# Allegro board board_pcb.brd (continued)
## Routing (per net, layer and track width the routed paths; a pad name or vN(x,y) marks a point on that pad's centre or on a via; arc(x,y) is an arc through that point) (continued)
FMC_D15: length 45.5
  TOP w0.152: U1.T16 v2(58.07,69.25) ; U2.R2 v2(72.49,69.63)
  ART08 w0.114: v2(72.49,69.63) 73.16,69.63 73.28,69.75 73.28,70.76 73.05,70.99 72.63,70.99 72.52,70.88 72.52,70.17 72.41,70.05 72.18,70.05 72.06,70.17 72.06,70.88 71.95,70.99 71.24,70.99 71.12,71.11 71.12,72.12 71.01,72.24 70.78,72.24 70.67,72.12 70.67,71.11 70.55,70.99 70.32,70.99 70.21,71.11 70.21,72.12 70.09,72.24 69.87,72.24 69.75,72.12 69.75,71.11 69.64,70.99 69.41,70.99 69.29,71.11 69.29,72.12 69.18,72.24 68.95,72.24 68.84,72.12 68.84,71.11 68.72,70.99 68.49,70.99 68.38,71.11 68.38,72.12 68.27,72.24 68.04,72.24 67.92,72.12 67.92,71.11 67.81,70.99 67.58,70.99 67.47,71.11 67.47,72.12 67.35,72.24 67.12,72.24 67.01,72.12 67.01,71.11 66.89,70.99 66.67,70.99 66.55,71.11 66.55,72.12 66.44,72.24 66.21,72.24 66.09,72.12 66.09,71.11 65.98,70.99 65.75,70.99 65.64,71.11 65.64,72.12 65.52,72.24 65.29,72.24 65.18,72.12 65.18,71.11 65.07,70.99 64.84,70.99 64.72,71.11 64.72,72.12 64.61,72.24 64.38,72.24 64.27,72.12 64.27,71.11 64.15,70.99 62.22,70.99 62.1,71.11 62.1,71.97 61.99,72.09 61.76,72.09 61.64,71.97 61.64,71.11 61.53,70.99 61.3,70.99 61.19,71.11 61.19,71.97 61.07,72.09 60.84,72.09 60.73,71.97 60.73,71.11 60.62,70.99 60.39,70.99 60.27,71.11 60.27,71.97 60.16,72.09 59.93,72.09 59.81,71.97 59.81,71.11 59.7,70.99 59.41,70.99 59.3,70.88 59.3,69.08 59.05,68.83 58.48,68.83 v2(58.07,69.25)
FMC_D16: length 45.6
  TOP w0.152: U1.T13 v2(58.07,66.85) ; U2.E8 v2(68.48,60.83)
  ART08 w0.114: v2(58.07,66.85) 57.83,66.85 57.42,66.43 57.06,66.43 56.87,66.24 56.87,65.89 56.62,65.63 56.26,65.63 56.06,65.43 56.06,65.07 55.83,64.85 55.45,64.85 55.12,64.52 55.12,60.96 55.24,60.83 55.93,60.83 56.08,60.68 56.08,59.44 56.29,59.23 56.81,59.23 57.02,59.44 57.39,59.44 57.71,59.12 57.71,58.56 57.82,58.45 58.07,58.45 58.19,58.56 58.19,59.58 58.3,59.69 58.53,59.69 58.64,59.58 58.64,58.56 58.76,58.45 59.11,58.45 59.23,58.56 59.23,59.6 59.34,59.72 59.57,59.72 59.69,59.6 59.69,58.18 59.8,58.06 60.09,58.06 60.21,58.18 60.21,58.48 60.32,58.6 60.55,58.6 60.66,58.48 60.66,58.18 60.78,58.06 61.15,58.06 61.26,58.18 61.26,59.6 61.38,59.72 61.61,59.72 61.72,59.6 61.72,58.18 61.83,58.06 62.06,58.06 62.18,58.18 62.18,59.6 62.29,59.72 62.52,59.72 62.63,59.6 62.63,58.18 62.75,58.06 62.98,58.06 63.09,58.18 63.09,59.6 63.21,59.72 63.43,59.72 63.55,59.6 63.55,58.18 63.66,58.06 63.89,58.06 64.01,58.18 64.01,59.6 64.12,59.72 64.35,59.72 64.46,59.6 64.46,58.18 64.58,58.06 64.88,58.06 65,58.18 65,59.61 66.62,61.24 67.33,61.24 67.45,61.13 67.45,60.9 67.56,60.78 67.79,60.78 67.9,60.9 67.9,61.13 68.02,61.24 68.37,61.24 68.48,61.13 v2(68.48,60.83)
FMC_D17: length 45.7
  TOP w0.152: U1.R13 v2(57.27,66.85) ; U2.D7 v2(69.28,60.03)
  ART08 w0.114: v2(57.27,66.85) 57.04,66.85 56.64,66.45 54.89,66.45 54.74,66.29 54.74,64.77 54.56,64.59 53.92,64.59 53.77,64.44 53.77,64.16 53.89,64.04 54.6,64.04 54.71,63.93 54.71,63.7 54.6,63.59 53.89,63.59 53.77,63.47 53.77,63.24 53.89,63.13 54.6,63.13 54.71,63.01 54.71,62.79 54.6,62.67 53.89,62.67 53.77,62.56 53.77,62.33 53.89,62.21 54.6,62.21 54.71,62.1 54.71,61.87 54.6,61.76 53.89,61.76 53.77,61.64 53.77,61.01 53.85,60.93 54.38,60.93 55.27,60.05 55.27,57.9 55.38,57.78 55.62,57.78 55.73,57.9 55.73,58.33 55.85,58.45 56.07,58.45 56.19,58.33 56.19,57.77 56.3,57.66 56.53,57.66 56.65,57.77 56.65,58.33 56.76,58.45 56.99,58.45 57.1,58.33 57.1,57.77 57.22,57.66 57.38,57.66 57.48,57.56 57.48,57.18 57.63,57.02 57.91,57.02 58.03,57.14 58.03,57.57 58.14,57.68 58.37,57.68 58.49,57.57 58.49,57.26 58.6,57.15 58.83,57.15 58.94,57.26 58.94,57.57 59.06,57.68 59.29,57.68 59.4,57.57 59.4,57.26 59.51,57.15 59.74,57.15 59.86,57.26 59.86,57.57 59.97,57.68 60.2,57.68 60.31,57.57 60.31,57.26 60.43,57.15 60.66,57.15 60.77,57.26 60.77,57.57 60.89,57.68 61.11,57.68 61.23,57.57 61.23,57.26 61.34,57.15 61.57,57.15 61.69,57.26 61.69,57.57 61.8,57.68 62.03,57.68 62.14,57.57 62.14,57.26 62.26,57.15 62.49,57.15 62.6,57.26 62.6,57.57 62.71,57.68 62.94,57.68 63.06,57.57 63.06,57.26 63.17,57.15 63.4,57.15 63.51,57.26 63.51,57.57 63.63,57.68 63.86,57.68 63.97,57.57 63.97,57.26 64.09,57.15 64.31,57.15 64.43,57.26 64.43,57.57 64.54,57.68 64.77,57.68 64.89,57.57 64.89,57.26 65,57.15 65.32,57.15 65.43,57.26 65.43,59.44 66.42,60.43 67.29,60.43 67.41,60.31 67.41,60.13 67.52,60.02 67.75,60.02 67.86,60.13 67.86,60.31 67.98,60.43 68.89,60.43 v2(69.28,60.03)
FMC_D18: length 45.8
  TOP w0.152: U2.D8 v2(68.48,60.03) ; U1.P13 v2(56.47,66.85)
  ART08 w0.114: v2(68.48,60.03) 68.1,59.64 66.55,59.64 65.81,58.9 65.81,56.36 65.68,56.24 65.46,56.24 65.35,56.35 65.35,56.65 65.24,56.77 65.01,56.77 64.89,56.65 64.89,56.35 64.78,56.24 64.55,56.24 64.44,56.35 64.44,56.65 64.32,56.77 64.09,56.77 63.98,56.65 63.98,56.35 63.86,56.24 63.64,56.24 63.52,56.35 63.52,56.65 63.41,56.77 63.18,56.77 63.06,56.65 63.06,56.35 62.95,56.24 62.72,56.24 62.61,56.35 62.61,56.65 62.49,56.77 62.26,56.77 62.15,56.65 62.15,56.35 62.04,56.24 61.81,56.24 61.69,56.35 61.69,56.65 61.58,56.77 61.35,56.77 61.24,56.65 61.24,56.35 61.12,56.24 60.89,56.24 60.78,56.35 60.78,56.65 60.66,56.77 60.44,56.77 60.32,56.65 60.32,56.35 60.21,56.24 59.98,56.24 59.86,56.35 59.86,56.65 59.75,56.77 59.52,56.77 59.41,56.65 59.41,56.35 59.28,56.23 59.28,55.99 59.17,55.88 58.47,55.88 57.94,56.41 57.1,56.41 56.97,56.54 56.97,56.72 56.85,56.85 55.8,56.85 54.48,58.17 54.48,58.39 54.6,58.5 54.75,58.5 54.86,58.61 54.86,58.84 54.75,58.96 54.6,58.96 54.48,59.07 54.48,60.25 54.25,60.48 53.42,60.48 52.86,61.04 52.86,64.89 52.97,65 54.24,65 54.36,65.12 54.36,65.34 54.24,65.46 52.59,65.46 52.48,65.57 52.48,65.8 52.59,65.92 54.24,65.92 54.36,66.03 54.36,66.26 54.24,66.37 52.97,66.37 52.86,66.49 52.86,67.11 52.98,67.23 55.88,67.23 56.27,66.85 v2(56.47,66.85)
FMC_D19: length 45.6
  TOP w0.152: U1.P14 v2(56.47,67.65) ; U2.B9 v2(66.89,58.43)
  ART08 w0.114: v2(66.89,58.43) 66.5,58.04 66.5,55.68 66.34,55.52 63.2,55.52 62.91,55.24 62.75,55.24 62.54,55.45 62.38,55.45 62.22,55.29 62.22,55.12 62.43,54.92 62.43,54.76 61.95,54.28 61.01,54.28 60.86,54.43 60.86,54.81 60.58,55.09 59.11,55.09 58.98,54.97 55.55,54.97 55.07,55.45 55.07,56.08 54.74,56.41 54.13,56.41 53.67,56.87 53.67,57.48 53.52,57.63 52.98,57.63 52.86,57.76 52.86,59.92 51.26,61.52 51.26,64.9 51.14,65.01 50.79,65.01 50.67,65.13 50.67,65.35 50.79,65.47 51.14,65.47 51.26,65.58 51.26,65.81 51.14,65.93 50.79,65.93 50.67,66.04 50.67,66.27 50.79,66.38 51.14,66.38 51.26,66.5 51.26,68.72 51.49,68.95 51.49,69.63 51.6,69.75 51.83,69.75 51.94,69.63 51.94,68.95 52.06,68.83 52.85,68.83 52.97,68.95 52.97,69.58 53.08,69.7 53.31,69.7 53.42,69.58 53.42,68.95 53.54,68.83 53.77,68.83 53.88,68.95 53.88,69.58 54,69.7 54.22,69.7 54.34,69.58 54.34,68.95 54.45,68.83 55.93,68.83 56.07,68.7 56.07,68.29 56.47,67.89 v2(56.47,67.65)
FMC_D20: length 45.6
  TOP w0.152: U1.R14 v2(57.27,67.65) ; U2.C8 v2(68.48,59.23)
  ART08 w0.114: v2(57.27,67.65) 56.86,67.23 56.29,67.23 56.06,67.46 56.06,67.89 55.91,68.05 53.01,68.05 52.9,68.16 52.9,68.36 52.78,68.48 52.55,68.48 52.44,68.36 52.44,68.16 52.32,68.05 52.2,68.05 52.07,67.92 52.07,67.3 51.96,67.19 51.75,67.19 51.64,67.07 51.64,66.85 51.75,66.73 51.96,66.73 52.07,66.62 52.07,66.39 51.96,66.27 51.75,66.27 51.64,66.16 51.64,65.93 51.75,65.82 51.96,65.82 52.07,65.7 52.07,65.47 51.96,65.36 51.75,65.36 51.64,65.25 51.64,65.02 51.75,64.9 51.96,64.9 52.07,64.79 52.07,61.29 53.23,60.13 53.53,60.13 53.67,59.99 53.67,57.91 53.92,57.66 54.37,57.66 54.48,57.54 54.48,57.07 55.17,56.39 55.77,56.39 55.88,56.27 55.88,55.44 55.99,55.32 56.36,55.32 56.48,55.44 56.48,55.92 56.59,56.03 56.82,56.03 56.94,55.92 56.94,55.44 57.05,55.32 57.28,55.32 57.39,55.44 57.39,55.92 57.51,56.03 57.74,56.03 57.85,55.92 57.85,55.44 57.96,55.32 58.47,55.32 58.65,55.5 59.54,55.5 59.65,55.61 59.65,55.77 59.77,55.88 60,55.88 60.11,55.77 60.11,55.61 60.22,55.5 60.45,55.5 60.57,55.61 60.57,55.77 60.68,55.88 60.91,55.88 61.02,55.77 61.02,55.61 61.14,55.5 61.27,55.5 61.38,55.38 61.38,54.8 61.5,54.69 61.72,54.69 61.84,54.8 61.84,55.77 61.95,55.88 66.03,55.88 66.14,55.99 66.14,58.29 66.67,58.83 67.27,58.83 67.38,58.71 67.38,58.46 67.5,58.34 67.72,58.34 67.84,58.46 67.84,58.71 67.95,58.83 68.08,58.83 v2(68.48,59.23)
FMC_D21: length 45.5
  TOP w0.152: U2.A9 v2(66.89,57.63) ; U1.D16 v2(47.67,69.25)
  ART08 w0.114: v2(47.67,69.25) 48.08,68.83 48.08,67.44 48.26,67.26 48.82,67.26 48.93,67.15 49.09,67.15 49.38,67.45 49.54,67.45 49.71,67.29 49.71,67.13 49.41,66.83 49.41,66.67 50.29,65.79 50.29,62.05 52.07,60.27 52.07,57.4 52.63,56.85 53.21,56.85 53.72,56.34 53.72,56.21 55.37,54.56 59.26,54.56 59.44,54.74 60.3,54.74 60.45,54.58 60.45,54.1 60.6,53.95 62.1,53.95 63.32,55.17 67.02,55.17 67.13,55.28 67.13,55.77 67.25,55.88 67.48,55.88 67.59,55.77 67.59,55.28 67.71,55.17 67.93,55.17 68.05,55.28 68.05,55.77 68.16,55.88 68.39,55.88 68.51,55.77 68.51,55.28 68.62,55.17 68.85,55.17 68.96,55.28 68.96,55.77 69.08,55.88 69.31,55.88 69.42,55.77 69.42,55.28 69.53,55.17 69.8,55.17 69.98,55.35 69.98,56.27 69.86,56.39 67.78,56.39 67.67,56.5 67.67,56.62 67.55,56.73 67.48,56.73 67.36,56.84 67.36,57.07 67.48,57.19 67.55,57.19 67.67,57.3 67.67,57.51 67.55,57.63 v2(66.89,57.63)
FMC_D22: length 45.6
  TOP w0.152: U1.B17 v2(46.07,70.05) ; U2.C7 v2(69.28,59.23)
  ART08 w0.114: v2(46.07,70.05) U1.B17 47.07,69.65 47.27,69.44 47.27,69.06 47.62,68.71 47.62,67.11 48.31,66.42 49.15,66.42 49.96,65.61 49.96,61.9 51.69,60.17 51.69,57.15 53.57,55.27 53.57,55 53.68,54.89 54.52,54.89 55.22,54.19 58.99,54.19 59.61,53.57 62.26,53.57 63.45,54.76 69.96,54.76 70.71,55.51 70.71,56.52 70.46,56.77 68.31,56.77 68.05,57.04 68.05,57.85 68.24,58.04 68.76,58.04 68.88,58.17 68.88,58.83 v2(69.28,59.23)
FMC_D23: length 45.7
  TOP w0.152: U1.B16 v2(46.07,69.25) ; U2.A8 v2(68.48,57.63)
  ART08 w0.114: v2(46.07,69.25) 46.48,68.83 47.07,68.83 47.27,68.63 47.27,67.03 48.08,66.22 48.08,65.84 48.26,65.66 48.64,65.66 48.9,65.41 48.9,62.99 49.58,62.31 49.58,61.67 50.47,60.78 50.47,57.84 50.65,57.66 51.08,57.66 51.27,57.47 51.27,57.09 53.19,55.17 53.19,54.84 53.47,54.56 54.28,54.56 54.74,54.1 54.74,53.31 54.97,53.09 62.76,53.09 63.3,53.62 69.32,53.62 69.62,53.92 70.98,53.92 71.09,54.04 71.09,55.09 71.21,55.21 71.39,55.21 71.5,55.32 71.5,55.55 71.39,55.66 71.21,55.66 71.09,55.78 71.09,56.01 71.21,56.12 71.39,56.12 71.5,56.24 71.5,56.46 71.39,56.58 71.21,56.58 71.09,56.69 71.09,56.95 70.89,57.15 68.96,57.15 v2(68.48,57.63)
FMC_D24: length 47.5
  TOP w0.152: U2.A2 v2(72.49,57.63) ; U1.A16 v2(45.27,69.25)
  ART03 w0.114: v2(45.27,69.25) 45.67,69.64 45.67,70.28 46.46,71.07 46.94,71.07 48.3,72.43 arc(50.51,73.9) 53.11,74.42 62.23,74.42 arc(67.11,73.45) 71.25,70.69 72.09,69.85 72.09,69.49 72.34,69.24 72.69,69.24 72.91,69.02 arc(73.07,68.79) 73.13,68.5 73.13,66 73.01,65.89 72.5,65.89 72.39,65.77 72.39,65.54 72.5,65.43 73.01,65.43 73.13,65.32 73.13,65.09 73.01,64.97 72.5,64.97 72.39,64.86 72.39,64.63 72.5,64.52 73.01,64.52 73.13,64.4 73.13,63.53 73.68,62.97 73.68,58.83 v2(72.49,57.63)
FMC_D25: length 47.4
  TOP w0.152: U1.A15 v2(45.27,68.45) ; U2.C3 v2(71.69,59.23)
  ART03 w0.114: v2(71.69,59.23) 71.69,58.94 71.8,58.83 72.95,58.83 73.23,59.11 73.23,61.87 72.64,62.46 72.64,62.62 72.87,62.86 72.87,63.02 72.71,63.18 72.55,63.18 72.32,62.95 72.15,62.95 71.99,63.11 71.99,63.27 72.23,63.5 72.23,63.66 72.06,63.83 71.9,63.83 71.67,63.59 71.51,63.59 71.27,63.83 71.27,70.03 70.65,70.65 arc(67.77,72.58) 64.37,73.25 56.18,73.25 55.52,73.91 52.83,73.91 arc(50.58,73.47) 48.67,72.19 47.1,70.62 46.82,70.62 46.48,70.28 46.48,68.24 46.16,67.92 45.8,67.92 v2(45.27,68.45)
FMC_D26: length 47.6
  TOP w0.152: U1.B15 v2(46.07,68.45) ; U2.A1 v2(74.08,57.63)
  ART03 w0.114: v2(74.08,57.63) 74.23,57.77 arc(74.43,58.07) 74.5,58.42 74.5,62.36 arc(74.43,62.69) 74.25,62.96 73.98,63.23 arc(73.74,63.59) 73.66,64 73.66,67.71 arc(73.42,68.94) 72.72,69.97 71.79,70.9 arc(68.12,73.53) 63.8,74.82 arc(63.54,74.85) 63.28,74.85 53.28,74.85 arc(49.74,74.15) 46.75,72.15 45.02,70.42 arc(44.88,70.21) 44.83,69.97 44.83,69.09 45.09,68.83 45.25,68.83 arc(45.65,68.76) 45.98,68.53 v2(46.07,68.45)
FMC_D27: length 47.6
  TOP w0.152: U1.C14 v2(46.87,67.65) ; U2.C2 v2(72.49,59.23)
  ART03 w0.114: v2(72.49,59.23) 72.9,59.64 72.9,61.75 72.62,62.03 71.03,62.03 70.89,62.17 70.89,66.16 70.78,66.27 70.4,66.27 70.28,66.39 70.28,66.62 70.4,66.73 70.78,66.73 70.89,66.85 70.89,67.08 70.78,67.19 70.4,67.19 70.28,67.3 70.28,67.53 70.4,67.65 70.78,67.65 70.89,67.76 70.89,67.99 70.78,68.1 70.4,68.1 70.28,68.22 70.28,68.45 70.4,68.56 70.78,68.56 70.89,68.68 70.89,68.9 70.78,69.02 70.4,69.02 70.28,69.13 70.28,69.36 70.4,69.48 70.78,69.48 70.89,69.59 70.89,69.77 70.13,70.54 arc(68.36,71.72) 66.27,72.14 65.84,72.14 65.73,72.25 65.73,72.5 65.61,72.62 65.39,72.62 65.27,72.5 65.27,72.25 65.16,72.14 64.93,72.14 64.81,72.25 64.81,72.5 64.7,72.62 64.47,72.62 64.36,72.5 64.36,72.25 64.24,72.14 62.41,72.14 61.72,72.82 55.93,72.82 55.27,73.48 52.86,73.48 arc(50.75,73.06) 48.95,71.86 47.27,70.18 47.27,68.25 46.87,67.85 v2(46.87,67.65)
FMC_D28: length 47.4
  TOP w0.152: U2.B1 v2(74.08,58.43) ; U1.A2 v2(45.27,57.25)
  ART03 w0.114: v2(74.08,58.43) 73.15,57.49 73.15,52.92 73.04,52.81 72.71,52.81 72.59,52.69 72.59,52.44 72.48,52.32 72.25,52.32 72.13,52.44 72.13,52.69 72.02,52.81 70.43,52.81 70.13,52.5 69.94,52.5 69.83,52.62 69.83,53.07 69.72,53.19 69.49,53.19 69.37,53.07 69.37,52.62 69.26,52.5 69.03,52.5 68.92,52.62 68.92,53.07 68.8,53.19 68.57,53.19 68.46,53.07 68.46,52.62 68.34,52.5 68.11,52.5 68,52.62 68,53.07 67.89,53.19 67.66,53.19 67.54,53.07 67.54,52.62 67.43,52.5 67.2,52.5 67.09,52.62 67.09,53.07 66.97,53.19 66.74,53.19 66.63,53.07 66.63,52.62 66.51,52.5 66.29,52.5 66.17,52.62 66.17,53.07 66.06,53.19 65.83,53.19 65.71,53.07 65.71,52.62 65.6,52.5 63.22,52.5 62.66,53.06 58.7,53.06 57.66,54.1 56.57,54.1 56.08,54.58 56.08,57.45 54.31,59.23 52.3,59.23 51.51,58.45 50.69,58.45 50.47,58.23 50.47,57.84 50.29,57.66 49.91,57.66 49.66,57.4 49.66,56.98 49.54,56.87 45.65,56.87 v2(45.27,57.25)
FMC_D29: length 47.5
  TOP w0.152: U1.B3 v2(46.07,58.05) ; U2.D2 v2(72.49,60.03)
  ART03 w0.114: v2(46.07,58.05) 46.46,57.66 49.53,57.66 49.66,57.78 49.66,58.29 49.81,58.45 50.27,58.45 50.47,58.65 50.47,59 50.72,59.26 51.49,59.26 52.27,60.05 54.25,60.05 54.48,59.82 54.48,59.44 56.18,57.73 56.62,57.73 56.85,57.51 56.85,56.01 56.73,55.9 56.63,55.9 56.52,55.79 56.52,55.56 56.63,55.44 56.73,55.44 56.85,55.33 56.85,54.72 56.96,54.61 57.78,54.61 58.58,53.81 58.74,53.81 58.86,53.93 58.86,54.42 58.97,54.53 59.2,54.53 59.32,54.42 59.32,53.81 59.43,53.7 60.34,53.7 60.46,53.81 60.46,54.34 60.57,54.46 60.8,54.46 60.91,54.34 60.91,53.81 61.03,53.7 61.26,53.7 61.37,53.81 61.37,54.34 61.48,54.46 61.71,54.46 61.83,54.34 61.83,53.81 61.94,53.7 62.17,53.7 62.28,53.81 62.28,54.34 62.4,54.46 62.63,54.46 62.74,54.34 62.74,53.81 62.86,53.7 68.61,53.7 68.83,53.92 72.44,53.92 72.67,54.15 72.67,57.09 72.56,57.2 71.39,57.2 71.27,57.32 71.27,59.46 71.45,59.64 72.1,59.64 v2(72.49,60.03)
FMC_D30: length 47.5
  TOP w0.152: U2.D3 v2(71.69,60.03) ; U1.E2 v2(49.27,58.05)
  ART03 w0.114: v2(71.69,60.03) 71.03,60.03 70.8,59.8 70.65,59.8 70.54,59.68 70.54,59.46 70.65,59.34 70.8,59.34 70.92,59.23 70.92,59 70.8,58.88 70.65,58.88 70.54,58.77 70.54,58.54 70.65,58.43 70.8,58.43 70.92,58.31 70.92,58.08 70.8,57.97 70.65,57.97 70.54,57.86 70.54,57.63 70.65,57.51 70.8,57.51 70.92,57.4 70.92,57.17 70.8,57.06 70.65,57.06 70.54,56.94 70.54,56.71 70.65,56.6 72.07,56.6 72.19,56.48 72.19,56.26 72.07,56.14 70.09,56.14 69.98,56.03 69.98,55.8 70.09,55.68 72.07,55.68 72.19,55.57 72.19,55.16 72.07,55.04 59.38,55.04 59.27,55.16 59.27,55.89 59.15,56.01 58.92,56.01 58.81,55.89 58.81,55.16 58.7,55.04 58.47,55.04 58.35,55.16 58.35,55.89 58.24,56.01 58.01,56.01 57.9,55.89 57.9,55.16 57.78,55.04 57.44,55.04 57.33,55.16 57.33,56.49 57.44,56.61 57.98,56.61 58.09,56.72 58.09,56.95 57.98,57.06 57.44,57.06 57.33,57.18 57.33,57.56 56.62,58.27 56.26,58.27 56.08,58.45 56.08,59.11 54.79,60.4 51.94,60.4 51.82,60.29 51.82,60.13 51.71,60.02 51.48,60.02 51.37,60.13 51.37,60.29 51.25,60.4 51,60.4 49.66,59.05 49.66,58.67 49.27,58.29 v2(49.27,58.05)
FMC_D31: length 47.5
  TOP w0.152: U1.F3 v2(49.27,58.85) ; U2.E2 v2(72.49,60.83)
  ART03 w0.114: v2(49.27,58.85) 49.27,59.05 50.98,60.76 54.81,60.76 56.31,59.26 56.64,59.26 56.87,59.03 56.87,58.67 58.47,57.07 59.19,57.07 59.31,56.96 59.31,56.53 59.42,56.41 59.75,56.41 59.86,56.3 59.86,55.66 59.98,55.55 60.21,55.55 60.32,55.66 60.32,56.3 60.44,56.41 60.66,56.41 60.78,56.3 60.78,55.66 60.89,55.55 61.12,55.55 61.24,55.66 61.24,56.3 61.35,56.41 61.58,56.41 61.69,56.3 61.69,55.66 61.81,55.55 62.04,55.55 62.15,55.66 62.15,56.3 62.27,56.41 62.49,56.41 62.61,56.3 62.61,55.66 62.72,55.55 62.95,55.55 63.07,55.66 63.07,56.3 63.18,56.41 63.41,56.41 63.52,56.3 63.52,55.66 63.64,55.55 63.87,55.55 63.98,55.66 63.98,56.3 64.09,56.41 64.32,56.41 64.44,56.3 64.44,55.66 64.55,55.55 64.78,55.55 64.89,55.66 64.89,56.3 65.01,56.41 65.24,56.41 65.35,56.3 65.35,55.66 65.47,55.55 65.69,55.55 65.81,55.66 65.81,56.3 65.92,56.41 66.15,56.41 66.27,56.3 66.27,55.66 66.38,55.55 66.61,55.55 66.72,55.66 66.72,56.3 66.84,56.41 67.07,56.41 67.18,56.3 67.18,55.66 67.29,55.55 67.52,55.55 67.64,55.66 67.64,56.3 67.75,56.41 67.98,56.41 68.09,56.3 68.09,55.66 68.21,55.55 68.44,55.55 68.55,55.66 68.55,56.3 68.67,56.41 68.89,56.41 69.01,56.3 69.01,55.66 69.12,55.55 69.35,55.55 69.47,55.66 69.47,56.58 69.58,56.69 69.99,56.69 70.1,56.81 70.1,60.07 70.86,60.83 v2(72.49,60.83)
FMC_NBL0: length 47.6
  TOP w0.152: U1.C4 v2(46.87,58.85) ; U2.K9 v2(66.89,65.63)
  ART03 w0.114: v2(46.87,58.85) U1.C4 47.27,59.84 47.5,60.07 48.64,60.07 48.9,60.33 48.9,60.83 49.71,61.65 56.69,61.65 56.87,61.47 56.87,60.25 58.52,58.6 59.03,58.6 59.21,58.42 66.24,58.42 66.62,58.04 67.3,58.04 67.42,57.92 67.42,57.8 67.53,57.68 67.76,57.68 67.87,57.8 67.87,57.92 67.99,58.04 68.77,58.04 68.88,58.15 68.88,61.35 69,61.46 70.17,61.46 70.28,61.58 70.28,61.81 70.17,61.92 69,61.92 68.88,62.04 68.88,62.84 69,62.95 70.14,62.95 70.26,63.07 70.26,63.29 70.14,63.41 69,63.41 68.88,63.52 68.88,63.75 69,63.87 70.14,63.87 70.26,63.98 70.26,64.21 70.14,64.32 69,64.32 68.88,64.44 68.88,64.67 69,64.78 70.14,64.78 70.26,64.89 70.26,65.12 70.14,65.24 69,65.24 68.88,65.35 68.88,65.93 68.77,66.04 67.3,66.04 v2(66.89,65.63)
FMC_NBL1: length 45.7
  TOP w0.152: U1.B4 v2(46.07,58.85) ; U2.K1 v2(74.08,65.63)
  ART08 w0.114: v2(74.08,65.63) 74.21,65.5 arc(74.63,64.87) 74.78,64.14 74.78,55.74 arc(74.72,55.47) 74.57,55.24 arc(74.42,55.02) 74.37,54.76 74.37,54.69 arc(74.25,54.1) 73.92,53.6 72.17,51.85 arc(71.77,51.58) 71.28,51.49 69.91,51.49 arc(69.69,51.44) 69.5,51.32 arc(69.35,51.23) 69.18,51.17 arc(69.12,51.16) 69.06,51.16 54.97,51.16 arc(54.8,51.19) 54.66,51.28 50.14,55.81 arc(49.91,55.95) 49.65,56.01 49.02,56.01 48.64,56.39 48.64,56.85 47.05,58.43 46.48,58.43 v2(46.07,58.85)
FMC_NBL2: length 45.7
  TOP w0.152: U2.F8 v2(68.48,61.63) ; U1.A4 v2(45.27,58.85)
  ART08 w0.114: v2(68.48,61.63) 70.61,61.63 70.99,61.24 71.97,61.24 72.09,61.13 72.09,57.22 72.2,57.1 72.4,57.1 72.52,56.99 72.52,56.76 72.4,56.64 72.2,56.64 72.09,56.53 72.09,55.04 72.26,54.86 72.26,53.07 71.97,52.78 69.93,52.78 69.65,52.5 61.7,52.5 61.04,51.84 55.09,51.84 54.36,52.58 54.36,53.98 54.1,54.23 53.21,54.23 52.81,54.64 52.81,55.07 51,56.87 49.05,56.87 47.27,58.65 47.27,59.03 47.05,59.25 U1.A4 v2(45.27,58.85)
FMC_NBL3: length 47.4
  TOP w0.152: U2.F2 v2(72.49,61.63) ; U1.A3 v2(45.27,58.05)
  ART03 w0.114: v2(72.49,61.63) 72.07,61.21 70.56,61.21 69.7,60.35 69.7,57.32 69.58,57.2 66.75,57.2 66.01,57.94 65.77,57.94 65.65,57.82 65.65,56.96 65.54,56.85 65.31,56.85 65.2,56.96 65.2,57.82 65.08,57.94 64.85,57.94 64.74,57.82 64.74,56.96 64.62,56.85 64.4,56.85 64.28,56.96 64.28,57.82 64.17,57.94 63.94,57.94 63.82,57.82 63.82,56.96 63.71,56.85 63.48,56.85 63.37,56.96 63.37,57.82 63.25,57.94 63.02,57.94 62.91,57.82 62.91,56.96 62.8,56.85 62.57,56.85 62.45,56.96 62.45,57.82 62.34,57.94 62.11,57.94 62,57.82 62,56.96 61.88,56.85 61.65,56.85 61.54,56.96 61.54,57.82 61.42,57.94 60.54,57.94 60.42,57.82 60.42,56.96 60.31,56.85 60.08,56.85 59.96,56.96 59.96,57.82 59.85,57.94 59.51,57.94 59.18,57.61 58.62,57.61 58.17,58.06 58.17,58.5 56.62,60.05 56.26,60.05 56.06,60.25 56.06,60.71 55.93,60.83 55.37,60.83 55.07,61.14 50.6,61.14 49.53,60.07 49.15,60.07 48.9,59.82 48.9,59.44 47.9,58.45 U1.A3 v2(45.27,58.05)
FMC_SDCKE0: length 41
  TOP w0.152: v1(56.26,53.59) 56.26,55.94 arc(56.25,56) 56.22,56.05 55.67,56.6 55.67,57.25 U1.N2 ; R1849.1 v1(79.88,65.15)
  ART06 w0.099: v1(56.26,53.59) 58.67,51.18 69.47,51.18 69.72,51.44 71.88,51.44 74.3,53.85 74.3,54.74 78.93,59.37 78.93,59.86 78.83,59.96 78.59,59.96 78.49,60.06 78.49,60.25 78.6,60.36 78.83,60.36 78.93,60.46 78.93,60.66 78.83,60.76 78.59,60.76 78.49,60.85 78.49,61.04 78.6,61.15 78.83,61.15 78.93,61.25 78.93,61.45 78.83,61.55 78.59,61.55 78.49,61.65 78.49,61.84 78.6,61.94 78.83,61.94 78.93,62.04 78.93,62.42 79.88,63.37 v1(79.88,65.15)
FMC_SDCLK: length 46.7
  TOP w0.152: U1.F15 v2(49.27,68.45) ; U2.J1 v2(74.08,64.83)
  ART06 w0.099: v2(49.27,68.45) 48.74,68.97 48.74,71.04 49.48,71.78 51.03,71.78 51.13,71.88 51.13,72.97 52.45,74.3 55.63,74.3 56.26,74.93 58.42,74.93 59.03,74.32 64.26,74.32 64.67,73.91 69.34,73.91 72.9,70.36 72.9,69.85 73,69.75 73.56,69.75 73.66,69.65 73.66,69.46 73.56,69.36 73,69.36 72.9,69.26 72.9,69.06 73,68.96 73.56,68.96 73.66,68.86 73.66,68.66 73.56,68.56 73,68.56 72.9,68.47 72.9,68.27 73,68.17 73.56,68.17 73.66,68.07 73.66,67.87 73.56,67.77 73,67.77 72.9,67.67 72.9,67.48 73,67.38 73.56,67.38 73.66,67.28 73.66,67.08 73.56,66.98 73,66.98 72.9,66.88 72.9,66.68 73,66.58 73.56,66.58 73.66,66.48 73.66,66.29 73.56,66.19 73,66.19 72.9,66.09 72.9,65.89 73,65.79 73.56,65.79 73.66,65.69 73.66,65.49 73.56,65.39 73,65.39 72.9,65.3 72.9,64.93 73,64.83 v2(74.08,64.83)
FMC_SDNCAS: length 46.6
  TOP w0.152: U2.K7 v2(69.28,65.63) ; U1.D6 v2(48.47,60.45)
  ART06 w0.099: v2(69.28,65.63) 69.28,65.88 70.15,66.75 70.15,66.92 70.25,67.02 70.34,67.02 70.43,67.12 70.43,67.31 70.34,67.41 70.25,67.41 70.15,67.51 70.15,67.71 70.25,67.81 70.34,67.81 70.43,67.91 70.43,68.11 70.34,68.21 70.25,68.21 70.15,68.3 70.15,68.5 70.25,68.6 70.34,68.6 70.43,68.7 70.43,68.9 70.34,69 70.25,69 70.15,69.1 70.15,69.29 70.25,69.39 70.34,69.39 70.43,69.49 70.43,69.69 70.34,69.79 70.25,69.79 70.15,69.89 70.15,70.79 69.95,70.99 62.06,70.99 61.96,71.09 61.96,71.48 61.86,71.58 61.66,71.58 61.56,71.48 61.56,71.09 61.46,70.99 61.13,70.99 61.03,71.09 61.03,72.7 60.93,72.8 60.74,72.8 60.64,72.7 60.64,71.09 60.54,70.99 60.2,70.99 60.05,71.15 60.05,72.72 59.95,72.82 59.66,72.82 59.56,72.72 59.56,72.13 59.46,72.03 59.27,72.03 59.17,72.13 59.17,72.72 59.07,72.82 53.8,72.82 53.34,72.36 52.78,72.36 52.57,72.15 52.57,70.8 52.07,70.31 52.07,67.06 48.9,63.88 48.9,60.87 v2(48.47,60.45)
FMC_SDNE0: length 47.7
  TOP w0.152: U2.J8 v2(68.48,64.03) ; U1.P2 v2(56.47,57.25)
  ART06 w0.099: v2(68.48,64.03) 68.89,63.63 69.34,63.63 69.98,62.99 69.98,62.1 69.79,61.91 69.79,61.66 69.44,61.32 69.19,61.32 68.88,61.01 68.88,60.58 69.01,60.45 69.52,60.45 69.7,60.28 69.7,60.11 69.8,60.01 70.61,60.01 70.71,59.91 70.71,59.71 70.61,59.61 69.8,59.61 69.7,59.52 69.7,59.32 69.8,59.22 70.61,59.22 70.71,59.12 70.71,58.92 70.61,58.82 69.8,58.82 69.7,58.72 69.7,58.53 69.8,58.43 70.61,58.43 70.71,58.33 70.71,58.13 70.61,58.03 69.8,58.03 69.7,57.93 69.7,57.73 69.8,57.63 70.61,57.63 70.71,57.53 70.71,57.34 70.61,57.24 69.8,57.24 69.7,57.14 69.7,56.94 69.8,56.84 70.61,56.84 70.71,56.74 70.71,56.54 70.61,56.44 69.6,56.44 69.16,56.01 68.88,56.01 68.78,56.11 68.78,57.13 68.68,57.23 68.48,57.23 68.39,57.13 68.39,56.11 68.29,56.01 68.09,56.01 67.99,56.11 67.99,57.13 67.89,57.23 67.69,57.23 67.59,57.13 67.59,56.11 67.49,56.01 67.3,56.01 67.2,56.11 67.2,57.13 67.1,57.23 66.9,57.23 66.8,57.13 66.8,56.11 66.7,56.01 66.5,56.01 66.4,56.11 66.4,57.13 66.31,57.23 66.11,57.23 66.01,57.13 66.01,56.11 65.91,56.01 58.24,56.01 58.14,56.11 58.14,56.52 58.05,56.62 57.85,56.62 57.75,56.52 57.75,56.11 57.65,56.01 57.45,56.01 57.35,56.11 57.35,56.52 57.25,56.62 57.06,56.62 56.96,56.52 56.96,56.11 56.86,56.01 56.23,56.01 55.83,56.41 55.65,56.41 55.58,56.49 55.58,56.77 55.67,56.87 56.09,56.87 v2(56.47,57.25)
  BOTTOM w0.152: v2(68.48,64.03) 67.87,64.64 R1835.1
FMC_SDNRAS: length 46.7
  TOP w0.152: U2.J9 v2(66.89,64.03) ; U1.T7 v2(58.07,61.25)
  ART06 w0.099: v2(66.89,64.03) 67.18,64.03 67.28,64.14 67.28,65.07 67.19,65.17 67,65.17 66.88,65.05 66.88,64.62 66.78,64.52 66.6,64.52 66.5,64.62 66.5,68.33 66.4,68.43 65.79,68.43 65.68,68.33 65.68,67.28 65.61,67.21 65.28,67.21 65.18,67.31 65.18,68.35 65.08,68.45 64.88,68.45 64.79,68.35 64.79,67.31 64.69,67.21 64.49,67.21 64.39,67.31 64.39,68.35 64.29,68.45 64.09,68.45 63.99,68.35 63.99,67.31 63.89,67.21 63.7,67.21 63.6,67.31 63.6,68.35 63.5,68.45 63.3,68.45 63.2,68.35 63.2,67.31 63.1,67.21 62.9,67.21 62.8,67.31 62.8,68.35 62.7,68.45 62.51,68.45 62.41,68.35 62.41,67.31 62.31,67.21 62.11,67.21 62.01,67.31 62.01,68.35 61.91,68.45 61.71,68.45 61.62,68.35 61.62,67.31 61.52,67.21 61.32,67.21 61.22,67.31 61.22,68.35 61.12,68.45 60.92,68.45 60.82,68.35 60.82,67.31 60.72,67.21 60.53,67.21 60.43,67.31 60.43,68.35 60.33,68.45 60.13,68.45 60.03,68.35 60.03,68.12 59.93,68.02 58.6,68.02 58.5,67.92 58.5,67.72 58.6,67.62 59.93,67.62 60.03,67.52 60.03,67.31 59.93,67.21 58.77,67.21 58.65,67.08 58.65,66.79 58.75,66.69 60.25,66.69 60.35,66.6 60.35,66.4 60.25,66.3 59.69,66.3 59.59,66.2 59.59,66 59.69,65.9 60.25,65.9 60.35,65.8 60.35,65.6 60.25,65.51 59.69,65.51 59.59,65.41 59.59,65.21 59.69,65.11 60.25,65.11 60.35,65.01 60.35,64.81 60.25,64.71 59.79,64.71 59.69,64.61 59.69,63.48 59.21,62.99 59.21,62.69 59.07,62.55 58.76,62.55 58.47,62.26 58.47,61.65 v2(58.07,61.25)
FMC_SDNWE: length 46.6
  TOP w0.152: v2(67.68,64.03) 67.68,64.83 U2.K8 ; U1.P4 v2(56.47,58.85)
  ART06 w0.099: v2(56.47,58.85) 56.8,58.85 56.9,58.75 56.9,58.4 56.8,58.3 56.31,58.3 56.21,58.21 56.21,58.01 56.31,57.91 56.8,57.91 56.9,57.81 56.9,57.1 57,57 57.38,57 57.48,57.1 57.48,57.91 57.58,58.01 57.78,58.01 57.88,57.91 57.88,57.1 57.98,57 58.28,57 58.38,57.1 58.38,57.53 58.48,57.63 58.68,57.63 58.78,57.53 58.78,57.1 58.88,57 59.08,57 59.18,57.1 59.18,57.53 59.27,57.63 59.54,57.63 59.64,57.53 59.64,56.64 59.74,56.54 59.93,56.54 60.03,56.64 60.03,57.53 60.13,57.63 60.33,57.63 60.43,57.53 60.43,56.64 60.53,56.54 60.73,56.54 60.83,56.64 60.83,57.53 60.93,57.63 61.12,57.63 61.22,57.53 61.22,56.64 61.32,56.54 61.52,56.54 61.62,56.64 61.62,57.53 61.72,57.63 61.92,57.63 62.02,57.53 62.02,56.64 62.11,56.54 62.31,56.54 62.41,56.64 62.41,57.53 62.51,57.63 62.71,57.63 62.81,57.53 62.81,56.64 62.91,56.54 63.1,56.54 63.2,56.64 63.2,57.53 63.3,57.63 63.5,57.63 63.6,57.53 63.6,56.64 63.7,56.54 63.9,56.54 64,56.64 64,57.53 64.1,57.63 64.29,57.63 64.39,57.53 64.39,56.64 64.49,56.54 64.69,56.54 64.79,56.64 64.79,57.53 64.89,57.63 65.09,57.63 65.19,57.53 65.19,56.64 65.28,56.54 65.48,56.54 65.58,56.64 65.58,57.53 65.68,57.63 66.37,57.63 66.75,58.01 67.53,58.01 67.63,58.11 67.63,58.35 67.73,58.45 67.93,58.45 68.03,58.35 68.03,58.11 68.13,58.01 68.73,58.01 68.88,58.17 68.88,60.15 68.61,60.43 68.28,60.43 68.1,60.6 68.1,60.99 68.33,61.21 68.71,61.21 69.72,62.23 69.72,62.87 69.34,63.25 68.59,63.25 68.49,63.35 68.49,63.5 68.39,63.6 68.2,63.6 68.1,63.5 68.1,63.35 68,63.25 67.78,63.25 67.68,63.35 v2(67.68,64.03)
GAUGE_ALCC: length 76.4
  TOP w0.152: v1(85.85,5.31) R1831.2 R1448.1 ; U1.C3 v2(46.87,58.05)
  ART08 w0.114: v2(46.87,58.05) 48.26,56.66 48.26,56.01 49.28,54.99 49.91,54.99 50.29,54.61 50.29,53.34 51.56,52.07 52.07,52.07 56.64,47.5 56.64,44.07 57.86,42.85 57.86,40.56 58.85,39.57 60.12,39.57 61.47,38.23 61.47,37.59 61.85,37.21 62.23,37.21 62.61,36.83 62.61,35.18 63.88,33.91 68.05,33.91 73.01,28.94 73.01,18.53 73.66,17.88 75.59,17.88 84.96,8.51 84.96,6.2 v1(85.85,5.31)
GAUGE_PULLUP: length 7.9
  TOP w0.305: R1700.2 84.71,6.86 ; R1699.2 v1(84.71,11.3) ; R1831.1 v1(85.85,6.12)
  ART03 w0.305: v1(84.71,11.3) 84.71,9.91 85.85,8.76 v1(85.85,6.12)
GAUGE_SCL: length 2
  TOP w0.152: R1813.1 R1699.1 R1450.1
GAUGE_SDA: length 2
  TOP w0.152: R1449.1 R1700.1 R1814.1
GPIO_0: length 10.7
  TOP w0.152: U134.6 7.62,49.15 6.86,49.91 6.86,51.82 J78.5
GPIO_1: length 22.3
  TOP w0.152: v1(8,54.61) 6.35,52.96 6.35,46.76 6.5,46.61 U134.7
  BOTTOM w0.152: 16.89,59.31 15.62,58.04 13.72,58.04 13.08,57.4 13.08,56.01 12.57,55.5 8.89,55.5 v1(8,54.61)
GPIO_2: length 19.1
  TOP w0.152: J78.3 5.46,52.96 5.46,42.55 6.48,41.53 U134.9
GPIO_3: length 21.2
  TOP w0.152: J78.1 4.83,54.86 4.83,40.51 6.35,38.99 8.38,38.99
GPIO_4: length 34.7
  TOP w0.152: U134.11 6.35,36.45 4.19,38.61 4.19,55.24 v1(4.06,55.37)
  BOTTOM w0.152: v1(4.06,55.37) 7.62,55.37 8,55.75 8,57.28 8.76,58.04 13.08,58.04 14.35,59.31
GPIO_5: length 47.9
  TOP w0.152: U134.22 v1(27.56,33.91)
  BOTTOM w0.152: J78.13 23.24,58.04 26.04,58.04 27.88,56.2 30.16,56.2 35.75,50.61 35.75,50.1 36.96,48.9 37.21,48.9 38.35,47.75 38.35,45.97 39.24,45.09 39.24,36.7 36.58,34.04 27.69,34.04 v1(27.56,33.91)
GPIO_6: length 43
  TOP w0.152: U134.23 v1(27.56,36.45)
  BOTTOM w0.152: J78.15 26.04,55.24 30.23,55.24 35.05,50.42 35.05,49.78 36.32,48.51 36.96,48.51 37.97,47.5 37.97,36.2 36.32,34.54 33.15,34.54 32.26,35.43 28.57,35.43 v1(27.56,36.45)
GPIO_7: length 53.8
  TOP w0.152: v1(27.56,38.35) 26.92,38.99 25.4,38.99
  BOTTOM w0.152: v1(27.56,38.35) 29.97,38.35 32.51,35.81 36.7,35.81 37.59,36.7 37.59,46.48 37.34,46.74 37.34,47.62 36.83,48.13 36.2,48.13 34.61,49.72 34.61,50.36 30.48,54.48 25.65,54.48 24.77,55.37 21.59,55.37 20.83,56.13 20.83,57.4 20.19,58.04 16.38,58.04 15.88,57.53 15.11,57.53 J78.7
I2C1_SCL: length 179.4
  TOP w0.152: U1.D5 v2(47.67,59.65) ; R1812.2 v1(88.65,102.87) ; R1814.2 v1(83.69,6.86)
  ART08 w0.114: v1(83.69,6.86) 79.1,11.46 76.15,11.46 72.01,15.6 72.01,28.19 70.74,29.46 69.72,29.46 66.42,32.77 62.23,32.77 60.07,34.92 60.07,35.05 56.9,38.23 56.9,42.11 55.7,43.31 55.7,47.17 51.82,51.05 51.31,51.05 48.72,53.64 48.72,54.41 47.62,55.5 44.96,55.5 44.32,56.13 44.32,59.56 44.98,60.22 45.75,60.22 45.97,60.45 47.07,60.45 47.67,59.85 v2(47.67,59.65) 48.13,59.18 48.56,59.18 48.9,59.51 48.9,60.58 48.63,60.85 48.27,60.85 48.08,61.04 48.08,62.28 47.82,62.55 46.55,62.55 44.62,64.48 35.85,64.48 34.67,65.66 34.67,66.55 v1(35.18,67.06)
  BOTTOM w0.152: v1(88.65,102.87) 87.38,104.14 67.18,104.14 56.56,93.51 55.97,93.51 49.15,86.7 49.15,83.36 49,83.21 44.86,83.21 43.18,81.53 43.18,79.12 42.29,78.23 40.56,78.23 37.47,75.14 37.47,69.34 v1(35.18,67.06)
I2C1_SDA: length 175.6
  TOP w0.152: R1811.2 v1(87.38,102.87) ; R1813.2 83.34,10.57 v1(82.68,9.91) ; U1.D4 v2(47.67,58.85)
  ART08 w0.114: v1(82.68,9.91) 80.49,12.09 76.17,12.09 72.52,15.75 72.52,28.47 67.72,33.27 63.75,33.27 61.47,35.56 61.47,36.83 61.09,37.21 59.31,37.21 59.18,37.34 59.18,38.05 57.28,39.95 57.28,42.7 56.16,43.81 56.16,47.35 51.94,51.56 51.56,51.56 49.91,53.21 49.91,54.23 49.53,54.61 49.02,54.61 47.75,55.88 45.21,55.88 44.83,56.26 44.83,59.05 45.62,59.84 46.25,59.84 46.48,60.07 47.03,60.07 47.27,59.83 47.27,59.49 47.67,59.09 v2(47.67,58.85) 48.69,58.85 49.1,59.26 49.61,59.26 49.78,59.44 49.78,59.82 49.25,60.35 49.25,61.39 49.02,61.62 49.02,62.1 48.69,62.43 48.31,62.43 47.75,62.99 46.61,62.99 44.58,65.02 36.07,65.02 v1(35.18,65.91)
  BOTTOM w0.152: v1(35.18,65.91) 37.97,68.71 37.97,74.93 40.77,77.72 42.39,77.72 43.69,79.02 43.69,81.51 45.01,82.83 49.5,82.83 49.66,82.98 49.66,86.49 55.56,92.39 56.2,92.39 67.44,103.63 86.61,103.63 v1(87.38,102.87)
ISINK_COARSE: length 4.1
  TOP w0.152: R1368.1 R1370.2 47,38.44 U117.5
ISINK_FINE: length 3.9
  TOP w0.152: U117.6 46.5,36.42 46.35,36.58 45.97,36.58 45.19,37.36 R1367.1 44.7,38.46 44.7,38.71 R1369.1
JTCK: length 50
  TOP w0.152: U1.B14 46.07,67.65 45.46,67.65 45.16,67.94 v2(43.94,67.94) ; v1(46.74,80.14) 47.22,80.14 47.78,80.7 47.78,81.94 48.9,83.06 50.29,83.06 50.93,83.69 50.93,94.49 51.97,95.53 R1838.1 R1843.2 51.97,97.82 52.07,97.92 J56.1 51.18,100.71 51.18,101.98 51.69,102.49 52.86,102.49 53.98,103.62 J6.3
  BOTTOM w0.152: v1(46.74,80.14) 47.37,79.5 47.37,78.82 41.53,72.97 41.53,68.73 41.81,68.45 42.93,68.45 43.43,67.94 v2(43.94,67.94)
JTDI: length 41.2
  TOP w0.152: v1(57.15,97.66) R1839.2 56.64,96.93 56.16,96.44 56.16,95.63 52.32,91.8 52.32,83.31 50.29,81.28 49.78,81.28 49.2,80.7 49.2,79.55 v1(48.64,78.99) ; v1(44.07,73.41) 43.18,72.52 43.18,67.69 43.43,67.44 45.05,67.44 45.24,67.25 U1.A14
  BOTTOM w0.152: v1(48.64,78.99) 44.07,74.42 v1(44.07,73.41) ; J56.9 v1(57.15,97.66)
JTDO: length 54
  TOP w0.152: J56.3 R1842.2 53.11,96.93 52.7,96.52 52.7,94.87 51.44,93.6 51.44,83.57 50.42,82.55 49.4,82.55 48.21,81.36 48.21,80.59 47.17,79.55 45.77,79.55 v1(45.21,78.99) ; U1.C6 v2(47.67,60.45)
  BOTTOM w0.152: v1(45.21,78.99) 45.21,78.66 40.39,73.84 40.39,66.52 42.06,64.85 46.12,64.85 46.18,64.9 46.99,64.9 47.27,64.62 47.27,64.27 47.49,64.05 47.85,64.05 48.07,63.82 48.07,61.87 47.85,61.65 47.42,61.65 47.27,61.49 U1.C6 v2(47.67,60.45)
JTMS: length 53.3
  TOP w0.152: v1(48.64,80.14) 48.64,80.9 49.53,81.79 50.29,81.79 51.82,83.31 51.82,92.48 54.23,94.89 54.23,96.65 54.51,96.93 R1837.2 54.99,97.92 54.23,98.68 54.23,99.44 J56.5 55.12,99.31 55.12,98.96 55.65,98.42 57.66,98.42 58.17,98.93 58.17,102.11 57.91,102.36 55.88,102.36 55.24,103.01 J6.4 ; U1.C15 v2(46.87,68.45)
  BOTTOM w0.152: v2(46.87,68.45) 46.47,68.85 46.47,69.48 46.3,69.65 44.78,69.65 43.33,71.09 43.33,74.19 47.85,78.71 47.85,79.35 v1(48.64,80.14)
JTRST: length 7
  TOP w0.152: R1840.2 R1841.1 41.94,60.33 43.81,60.33 44.63,61.14 45.01,61.14 45.12,61.25 46.07,61.25 U1.B7
LCD_B0: length 121.2
  TOP w0.152: U1.D11 v2(47.67,65.25) ; J2.21 108.84,95.73 108.64,95.53 107.92,95.53 107.77,95.68 107.77,97.94 107.92,98.1 109.09,98.1 109.25,98.25 109.25,98.55 109.09,98.71 107.92,98.71 107.77,98.86 107.77,99.23 107.92,99.38 108.48,99.38 108.64,99.53 108.64,99.84 108.48,99.99 107.92,99.99 107.77,100.14 107.77,100.46 108.33,101.02 109.27,101.02 109.45,101.19 109.45,101.71 109.8,102.07 109.8,102.49 109.61,102.69 J1.21
  ART03 w0.114: v1(49.66,75.82) 49.07,75.82 48.56,75.31 47.75,75.31 44.17,71.73 44.17,68.99 45.97,67.18 45.97,66.27 46.76,65.48 47.43,65.48 v2(47.67,65.25)
  BOTTOM w0.152: v1(49.66,75.82) 49.66,77.09 54.29,81.72 54.29,86.19 55.34,87.24 55.34,87.46 54.86,87.94 54.86,88.15 55.07,88.37 55.29,88.37 55.77,87.89 55.99,87.89 56.2,88.1 56.2,88.32 55.72,88.8 55.72,89.02 55.93,89.23 56.15,89.23 56.63,88.75 56.85,88.75 57.06,88.97 57.06,89.18 56.58,89.66 56.58,89.88 56.8,90.1 57.01,90.1 57.49,89.61 57.71,89.61 58.98,90.88 58.98,91.09 58.66,91.41 58.66,91.63 58.87,91.84 59.09,91.84 59.41,91.53 59.62,91.53 59.84,91.74 59.84,91.96 59.52,92.27 59.52,92.49 59.74,92.71 59.95,92.71 60.27,92.39 60.49,92.39 60.7,92.6 60.7,92.82 60.38,93.14 60.38,93.35 60.6,93.57 60.81,93.57 61.13,93.25 61.35,93.25 61.56,93.47 61.56,93.68 61.25,94 61.25,94.22 61.46,94.43 61.68,94.43 62,94.11 62.21,94.11 62.43,94.33 62.43,94.54 62.11,94.86 62.11,95.08 62.32,95.29 62.54,95.29 62.86,94.98 63.07,94.98 63.58,95.48 63.58,96.19 70.03,102.64 81.89,102.64 82.22,102.31 88.85,102.31 90.73,104.19 102.74,104.19 108.84,98.09 J2.21
LCD_B1: length 121.2
  TOP w0.152: U1.E10 v2(48.47,64.45) ; J1.22 109.1,102.3 108.97,102.16 108.97,101.95 109.07,101.84 109.07,101.63 108.85,101.41 108.64,101.41 108.54,101.51 108.32,101.51 107.42,100.61 107.42,96.16 107.26,96.01 106.83,96.01 106.68,95.86 106.68,95.55 106.83,95.4 107.26,95.4 107.42,95.25 107.42,94.78 107.57,94.62 107.62,94.62 107.77,94.47 107.77,94.17 107.62,94.01 107.57,94.01 107.42,93.86 107.42,93.22 107.57,93.07 108.69,93.07 108.84,93.22 J2.22
  ART03 w0.114: v1(52.7,79.12) 50.42,76.83 48.82,76.83 48.23,76.25 46.2,76.25 43.31,73.36 43.31,68.55 43.51,68.35 43.51,67.44 46.25,64.69 46.25,64.4 46.61,64.05 48.07,64.05 v2(48.47,64.45)
  BOTTOM w0.152: v1(52.7,79.12) 52.7,79.32 54.97,81.58 54.97,85.93 64.54,95.5 64.54,95.71 64.35,95.91 64.35,96.12 64.56,96.34 64.78,96.34 64.97,96.15 65.18,96.15 65.4,96.36 65.4,96.58 65.21,96.77 65.21,96.98 65.42,97.2 65.64,97.2 65.83,97.01 66.05,97.01 66.26,97.22 66.26,97.44 66.07,97.63 66.07,97.85 66.29,98.06 66.5,98.06 66.69,97.87 66.91,97.87 67.12,98.09 67.12,98.3 66.93,98.49 66.93,98.71 67.15,98.92 67.36,98.92 67.56,98.73 67.77,98.73 67.99,98.95 67.99,99.16 67.8,99.36 67.8,99.57 68.01,99.79 68.23,99.79 68.42,99.6 68.63,99.6 68.85,99.81 68.85,100.03 68.66,100.22 68.66,100.43 68.87,100.65 69.09,100.65 69.28,100.46 69.5,100.46 69.71,100.67 69.71,100.89 69.52,101.08 69.52,101.3 69.74,101.51 69.95,101.51 70.14,101.32 70.36,101.32 71.22,102.18 81.74,102.18 81.97,101.96 89.33,101.96 91.06,103.68 102.54,103.68 107.78,98.44 107.78,95.54 J2.22
LCD_B2: length 121.5
  TOP w0.152: J1.23 108.61,102.31 107.06,100.76 107.06,98.22 106.91,98.07 106.56,98.07 106.41,98.22 106.41,99.75 106.25,99.9 105.95,99.9 105.8,99.75 105.8,98.22 105.18,97.61 105.18,95.73 105.38,95.53 106.14,95.53 106.3,95.69 106.3,97.03 ; U1.D10 v2(47.67,64.45)
  ART03 w0.114: v2(47.67,64.45) 47.22,64.9 46.71,64.9 44.7,66.9 44.7,67.82 43.74,68.78 43.74,71.93 47.59,75.78 48.43,75.78 49.02,76.38 51.1,76.38 v1(53.85,79.12)
  BOTTOM w0.152: 106.3,97.03 102.11,101.22 72.21,101.22 71.77,100.77 71.77,100.56 72.21,100.11 72.21,99.9 72,99.68 71.78,99.68 71.34,100.13 71.12,100.13 70.9,99.91 70.9,99.7 71.35,99.25 71.35,99.03 71.13,98.82 70.92,98.82 70.47,99.26 70.26,99.26 70.04,99.05 70.04,98.83 70.49,98.39 70.49,98.17 70.27,97.96 70.05,97.96 69.61,98.4 69.39,98.4 69.18,98.19 69.18,97.97 69.62,97.53 69.62,97.31 69.41,97.09 69.19,97.09 68.75,97.54 68.53,97.54 68.32,97.32 68.32,97.11 68.76,96.66 68.76,96.45 68.55,96.23 68.33,96.23 67.88,96.68 67.67,96.68 67.45,96.46 67.45,96.24 67.9,95.8 67.9,95.58 67.68,95.37 67.47,95.37 67.02,95.81 66.81,95.81 66.59,95.6 66.59,95.38 67.04,94.94 67.04,94.72 66.82,94.51 66.6,94.51 66.16,94.95 65.94,94.95 65.73,94.74 65.73,94.52 66.17,94.07 66.17,93.86 65.96,93.64 65.74,93.64 65.3,94.09 65.08,94.09 64.87,93.87 64.87,93.66 65.31,93.21 65.31,93 65.09,92.78 64.88,92.78 64.43,93.23 64.22,93.23 64,93.01 64,92.79 64.45,92.35 64.45,92.13 64.23,91.92 64.02,91.92 63.57,92.36 63.36,92.36 63.14,92.15 63.14,91.93 63.59,91.49 63.59,91.27 63.37,91.06 63.15,91.06 62.71,91.5 62.49,91.5 57.38,86.39 57.38,82.14 54.86,79.63 54.36,79.63 v1(53.85,79.12)
LCD_B3: length 121.2
  TOP w0.152: v2(43.94,64.01) 44.07,64.14 44.83,64.14 45.14,64.45 46.07,64.45 U1.B10 ; J1.24 108.1,102.34 106.07,100.3 105.64,100.3 105.41,100.08 105.41,98.37 104.8,97.76 104.8,96.23 104.65,96.08 104.29,96.08 104.14,95.93 104.14,95.63 104.29,95.47 104.65,95.47 104.8,95.32 104.8,93.19 104.95,93.04 106.15,93.04 106.3,93.19 106.3,94.49
  ART03 w0.114: v1(54.8,80.33) 52.51,80.33 50.04,77.85 48.39,77.85 47.75,77.22 45.85,77.22 41.53,72.9 41.53,66.42 v2(43.94,64.01)
  BOTTOM w0.152: 106.3,94.49 107.35,95.54 107.35,98.01 102.92,102.44 90.68,102.44 89.84,101.6 81.66,101.6 81.53,101.73 71.78,101.73 56.79,86.74 56.79,86.21 56.64,86.06 55.78,86.06 55.63,85.91 55.63,85.61 55.78,85.45 56.64,85.45 56.79,85.3 56.79,85 56.64,84.84 55.78,84.84 55.63,84.69 55.63,84.39 55.78,84.23 56.64,84.23 56.79,84.08 56.79,83.78 56.64,83.62 55.78,83.62 55.63,83.47 55.63,83.17 55.78,83.01 56.64,83.01 56.79,82.86 56.79,82.32 v1(54.8,80.33)
LCD_B4: length 121.3
  TOP w0.152: J2.25 103.76,95.68 103.61,95.53 102.84,95.53 102.69,95.68 102.69,97.82 103.05,98.17 104.7,98.17 105.05,98.53 105.05,98.8 104.9,98.95 103.99,98.95 103.84,99.1 103.84,99.41 103.99,99.56 104.9,99.56 105.05,99.71 105.05,100.38 105.47,100.8 106.01,100.8 107.61,102.4 J1.25 ; U1.C8 v2(46.87,62.05)
  ART03 w0.114: v1(56.64,80.26) 56.13,79.76 52.58,79.76 50.16,77.34 48.51,77.34 47.88,76.71 45.97,76.71 42.89,73.62 42.89,68.38 43.09,68.18 43.09,65.62 46.67,62.05 v2(46.87,62.05)
  BOTTOM w0.152: J2.25 103.76,97.41 102.11,99.06 100.3,99.06 98.96,100.41 86.51,100.41 85.8,99.69 84.77,99.69 84.62,99.85 84.62,100.23 84.47,100.38 84.16,100.38 84.01,100.23 84.01,99.85 83.86,99.69 82.77,99.69 82.62,99.85 82.62,100.23 82.47,100.38 82.16,100.38 82.01,100.23 82.01,100 81.86,99.85 81.4,99.85 81.25,100 81.25,100.15 81.1,100.3 80.79,100.3 80.64,100.15 80.64,100 80.49,99.85 80.19,99.85 80.03,100 80.03,100.15 79.88,100.3 79.58,100.3 79.42,100.15 79.42,100 79.27,99.85 78.97,99.85 78.81,100 78.81,100.15 78.66,100.3 78.36,100.3 78.2,100.15 78.2,100 78.05,99.85 77.75,99.85 77.59,100 77.59,100.15 77.44,100.3 77.14,100.3 76.98,100.15 76.98,100 76.83,99.85 76.53,99.85 76.38,100 76.38,100.15 76.22,100.3 75.92,100.3 75.77,100.15 75.77,100 75.61,99.85 75.06,99.85 74.41,99.2 74.2,99.2 73.93,99.47 73.71,99.47 73.5,99.25 73.5,99.04 73.76,98.77 73.76,98.56 73.55,98.34 73.33,98.34 73.07,98.61 72.85,98.61 72.64,98.39 72.64,98.18 72.9,97.91 72.9,97.69 72.69,97.48 72.47,97.48 72.2,97.74 71.99,97.74 71.77,97.53 71.77,97.31 72.04,97.05 72.04,96.83 71.82,96.61 71.61,96.61 71.34,96.88 71.13,96.88 70.91,96.67 70.91,96.45 71.18,96.18 71.18,95.97 70.96,95.75 70.75,95.75 70.48,96.02 70.26,96.02 70.05,95.8 70.05,95.59 70.31,95.32 70.31,95.1 70.1,94.89 69.88,94.89 69.62,95.16 69.4,95.16 69.18,94.94 69.18,94.72 69.45,94.46 69.45,94.24 69.24,94.03 69.02,94.03 68.75,94.29 68.54,94.29 68.32,94.08 68.32,93.86 68.59,93.6 68.59,93.38 68.37,93.16 68.16,93.16 67.89,93.43 67.68,93.43 67.46,93.22 67.46,93 67.73,92.73 67.73,92.52 67.51,92.3 67.3,92.3 67.03,92.57 66.81,92.57 66.6,92.35 66.6,92.14 66.86,91.87 66.86,91.65 66.65,91.44 66.43,91.44 66.17,91.71 65.95,91.71 65.73,91.49 65.73,91.27 66,91.01 66,90.79 65.79,90.58 65.57,90.58 65.3,90.84 65.09,90.84 64.87,90.63 64.87,90.41 65.14,90.14 65.14,89.93 64.85,89.64 62.53,89.64 59.84,86.94 59.84,83.46 v1(56.64,80.26)
LCD_B5: length 121.8
  TOP w0.152: U1.B8 46.07,62.05 44.65,62.05 v2(43.43,60.83) ; J2.26 103.76,93.8 103.38,93.42 102.51,93.42 102.31,93.62 102.31,95.27 102.16,95.42 101.75,95.42 101.6,95.57 101.6,95.88 101.75,96.03 102.16,96.03 102.31,96.18 102.31,97.94 103.35,98.98 103.35,99.44 105.21,101.3 105.94,101.3 106.19,101.54 106.19,101.76 106.18,101.77 106.18,101.99 106.39,102.2 106.61,102.2 106.62,102.19 106.84,102.19 107.1,102.46 J1.26
  ART03 w0.114: v2(43.43,60.83) 42.95,60.35 42.01,60.35 40.64,61.72 40.64,63.59 39.59,64.64 39.59,74.89 44.45,79.76 44.45,80.39 44.83,80.77 47.75,80.77 48.45,81.47 50.41,81.47 51.77,82.83 57.51,82.83 v1(57.91,82.42)
  BOTTOM w0.152: J2.26 104.45,95.79 104.79,96.61 104.83,96.77 104.83,97.18 104.75,97.56 104.08,98.23 102.94,99.16 102.12,99.72 99.35,100.86 74.17,100.86 63.72,90.41 62.37,90.41 59.13,87.17 59.13,86.21 58.98,86.06 58.67,86.06 58.52,85.9 58.52,85.6 58.67,85.45 58.98,85.45 59.13,85.29 59.13,84.99 58.98,84.84 58.67,84.84 58.52,84.68 58.52,84.38 58.67,84.23 58.98,84.23 59.13,84.07 59.13,83.64 v1(57.91,82.42)
LCD_B6: length 121
  TOP w0.152: v2(42.29,60.83) 43.12,61.66 43.68,61.66 44.46,62.45 U1.A8 ; J1.27 106.61,102.92 105.38,101.7 105,101.7 103,99.69 103,99.19 102.84,99.03 102.63,99.03 102.49,99.17 102.27,99.17 102.06,98.96 102.06,98.74 102.2,98.6 102.2,98.39 101.9,98.09 101.4,98.09 101.25,98.25 101.25,98.32 101.1,98.48 100.79,98.48 100.64,98.32 100.64,98.25 100.49,98.09 100.33,98.09 100.18,97.94 100.18,95.66 100.33,95.5 100.99,95.5 101.22,95.73 J2.27
  ART03 w0.114: v1(61.21,80.77) 60.07,81.92 56.95,81.92 56.46,82.4 52.04,82.4 50.61,80.96 48.58,80.96 47.12,79.5 44.83,79.5 44.45,79.12 44.45,77.72 40.06,73.33 40.06,64.77 41.21,63.61 41.21,61.91 v2(42.29,60.83)
  BOTTOM w0.152: v1(61.21,80.77) 61.47,81.03 61.47,86.74 63.25,88.52 66.67,88.52 67.05,88.9 67.27,88.9 67.49,88.68 67.7,88.68 67.92,88.9 67.92,89.11 67.7,89.33 67.7,89.55 67.92,89.76 68.13,89.76 68.35,89.55 68.56,89.55 68.78,89.76 68.78,89.98 68.56,90.19 68.56,90.41 68.78,90.62 69,90.62 69.21,90.41 69.43,90.41 69.64,90.62 69.64,90.84 69.43,91.06 69.43,91.27 69.64,91.49 69.86,91.49 70.07,91.27 70.29,91.27 70.51,91.49 70.51,91.7 70.29,91.92 70.29,92.13 70.51,92.35 70.72,92.35 70.94,92.13 71.15,92.13 71.37,92.35 71.37,92.56 71.15,92.78 71.15,93 71.37,93.21 71.58,93.21 71.8,93 72.02,93 72.23,93.21 72.23,93.43 72.01,93.64 72.01,93.86 72.23,94.07 72.45,94.07 72.66,93.86 72.88,93.86 73.09,94.07 73.09,94.29 72.88,94.51 72.88,94.72 73.09,94.94 73.31,94.94 73.52,94.72 73.74,94.72 73.96,94.94 73.96,95.15 73.74,95.37 73.74,95.58 73.96,95.8 74.17,95.8 74.39,95.58 74.6,95.58 74.82,95.8 74.82,96.01 74.6,96.23 74.6,96.45 74.82,96.66 75.03,96.66 75.25,96.45 75.47,96.45 75.68,96.66 75.68,96.88 75.46,97.09 75.46,97.31 75.68,97.52 75.9,97.52 76.11,97.31 76.33,97.31 76.54,97.52 76.54,97.74 76.33,97.96 76.33,98.17 76.54,98.39 76.76,98.39 76.98,98.17 77.19,98.17 77.88,98.86 86.77,98.86 87.4,99.49 97.84,99.49 100.3,97.03 J2.27
LCD_B7: length 122.1
  TOP w0.152: J1.28 106.1,102.93 105.23,102.06 104.65,102.06 101.5,98.91 99.89,98.91 99.62,98.64 99.03,98.64 98.88,98.49 98.88,98.18 99.03,98.03 99.62,98.03 99.77,97.88 99.77,94.72 100,94.49 J2.28 ; U1.C7 v2(47.67,61.25)
  ART03 w0.114: v2(47.67,61.25) U1.C7 46.3,61.65 44.58,63.37 42.93,63.37 41.01,65.29 41.01,73.01 45.85,77.85 47.62,77.85 48.13,78.36 49.91,78.36 52.45,80.9 57.28,80.9 v1(57.91,80.26)
  BOTTOM w0.152: J2.28 102.34,95.61 102.34,97.56 101.42,98.48 100.18,98.48 98.7,99.95 86.97,99.95 86.28,99.26 76.45,99.26 75.78,98.59 75.57,98.59 75.34,98.82 75.12,98.82 74.91,98.6 74.91,98.39 75.13,98.16 75.13,97.94 74.92,97.73 74.7,97.73 74.47,97.96 74.26,97.96 74.04,97.74 74.04,97.53 74.27,97.3 74.27,97.08 74.06,96.87 73.84,96.87 73.61,97.09 73.4,97.09 73.18,96.88 73.18,96.66 73.41,96.43 73.41,96.22 73.19,96 72.98,96 72.75,96.23 72.53,96.23 72.32,96.02 72.32,95.8 72.55,95.57 72.55,95.36 72.33,95.14 72.12,95.14 71.89,95.37 71.67,95.37 71.46,95.15 71.46,94.94 71.68,94.71 71.68,94.49 71.47,94.28 71.25,94.28 71.02,94.51 70.81,94.51 70.59,94.29 70.59,94.08 70.82,93.85 70.82,93.63 70.61,93.42 70.39,93.42 70.16,93.64 69.95,93.64 69.73,93.43 69.73,93.21 69.96,92.98 69.96,92.77 69.74,92.55 69.53,92.55 69.3,92.78 69.08,92.78 68.87,92.57 68.87,92.35 69.1,92.12 69.1,91.91 68.88,91.69 68.67,91.69 68.44,91.92 68.22,91.92 68.01,91.7 68.01,91.49 68.23,91.26 68.23,91.04 68.02,90.83 67.8,90.83 67.57,91.06 67.36,91.06 67.14,90.84 67.14,90.63 67.37,90.4 67.37,90.18 67.16,89.97 66.94,89.97 66.71,90.19 66.5,90.19 66.28,89.98 66.28,89.76 66.51,89.53 66.51,89.32 66.22,89.03 62.87,89.03 60.71,86.87 60.71,83.06 v1(57.91,80.26)
LCD_CLK: length 121.7
  TOP w0.152: J2.30 97.69,94.49 97.54,94.64 97.54,97.46 98.36,98.28 98.36,98.73 98.06,99.03 98.06,99.25 98.27,99.47 98.49,99.47 98.79,99.16 99.01,99.16 99.34,99.49 101.42,99.49 104.57,102.64 104.95,102.64 105.1,102.79 J1.30 ; U1.H3 v2(50.87,58.05)
  ART03 w0.114: v1(67.18,81.41) 66.29,82.3 63.88,82.3 61.59,84.58 49.78,84.58 48.39,83.19 44.83,83.19 37.97,76.33 37.97,64.14 38.99,63.12 38.99,61.47 40.66,59.8 40.66,59.16 44.77,55.05 48.45,55.05 48.95,54.56 50.29,54.56 51.82,56.08 51.82,57.1 v2(50.87,58.05)
  BOTTOM w0.152: J2.30 97.79,94.49 96.27,92.96 80.62,92.96 78.77,91.11 76.89,91.11 v1(67.18,81.41)
LCD_DE: length 122
  TOP w0.152: J1.34 103.1,102.9 101.49,101.29 arc(100.99,100.96) 100.4,100.84 97.04,100.84 95.07,100.02 92.71,97.66 92.53,97.23 92.53,96.79 93.41,94.68 93.6,94.49 ; U1.D7 v2(48.47,61.25)
  ART03 w0.114: v2(48.47,61.25) 48.29,61.25 47.89,60.85 46.47,60.85 44.45,62.87 42.66,62.87 40.5,65.02 40.5,73.14 45.72,78.36 47.12,78.36 48.39,79.63 50.29,79.63 52.02,81.36 58.34,81.36 v1(59.44,80.26)
  BOTTOM w0.152: v1(59.44,80.26) 59.56,80.14 61.59,80.14 62.48,81.03 62.48,87 63.24,87.76 65.45,87.76 65.61,87.6 65.61,87.4 65.76,87.25 66.06,87.25 66.22,87.4 66.22,87.6 66.37,87.76 67.49,87.76 68.35,88.62 68.57,88.62 68.86,88.33 69.07,88.33 69.29,88.54 69.29,88.76 69,89.05 69,89.27 69.21,89.48 69.43,89.48 69.72,89.19 69.94,89.19 70.15,89.4 70.15,89.62 69.86,89.91 69.86,90.13 70.08,90.34 70.29,90.34 70.58,90.05 70.8,90.05 71.01,90.27 71.01,90.48 70.72,90.78 70.72,90.99 70.94,91.21 71.15,91.21 71.45,90.91 71.66,90.91 71.88,91.13 71.88,91.35 71.58,91.64 71.58,91.85 71.8,92.07 72.02,92.07 72.31,91.78 72.52,91.78 72.74,91.99 72.74,92.21 72.45,92.5 72.45,92.72 72.66,92.93 72.88,92.93 73.17,92.64 73.39,92.64 73.6,92.86 73.6,93.07 73.31,93.36 73.31,93.58 73.53,93.79 73.74,93.79 74.03,93.5 74.25,93.5 74.46,93.72 74.46,93.93 74.17,94.23 74.17,94.44 74.39,94.66 74.6,94.66 74.9,94.36 75.11,94.36 75.33,94.58 75.33,94.8 75.03,95.09 75.03,95.3 75.25,95.52 75.47,95.52 75.76,95.23 75.97,95.23 76.19,95.44 76.19,95.66 75.9,95.95 75.9,96.17 76.11,96.38 76.33,96.38 76.62,96.09 76.84,96.09 77.05,96.31 77.05,96.52 76.76,96.81 76.76,97.03 76.98,97.24 77.19,97.24 77.48,96.95 77.7,96.95 77.91,97.17 77.91,97.38 77.62,97.68 77.62,97.89 77.84,98.11 78.05,98.11 78.35,97.81 78.56,97.81 79.22,98.48 87.07,98.48 87.63,99.03 94.21,99.03 94.74,98.5 94.74,95.63 93.6,94.49
LCD_G0: length 121.3
  TOP w0.152: U1.N14 v2(55.67,67.65) ; J1.13 113.61,102.63 113.82,102.41 114.05,102.41 114.37,102.09 114.37,101.86 114.69,101.54 114.91,101.54 115.23,101.23 115.23,101 115.55,100.68 115.78,100.68 116.09,100.37 116.09,100.14 117.48,98.75 117.48,97.99 117.63,97.84 117.94,97.84 118.09,97.99 118.09,98.76 118.24,98.91 118.55,98.91 118.7,98.76 118.7,98.22 118.85,98.07 119.16,98.07 119.31,98.22 119.31,98.76 119.46,98.91 120.22,98.91 120.6,98.53 120.6,98.12 120.09,97.61 120.09,97.18 119.94,97.03 J2.13
  BOTTOM w0.152: J2.13 117.75,97.03 117.5,96.77 117.5,94.01 116.73,93.23 116.04,93.23 112.89,90.08 91.35,90.08 89.78,88.51 89.57,88.51 89.03,89.05 88.82,89.05 88.6,88.83 88.6,88.62 89.14,88.08 89.14,87.87 88.92,87.65 88.7,87.65 88.17,88.18 87.96,88.18 87.74,87.97 87.74,87.75 88.27,87.22 88.27,87 88.06,86.79 87.84,86.79 87.31,87.32 87.09,87.32 86.88,87.11 86.88,86.89 87.41,86.36 87.41,86.14 87.19,85.92 86.98,85.92 86.45,86.46 86.23,86.46 86.01,86.24 86.01,86.03 86.55,85.49 86.55,85.28 86.33,85.06 86.12,85.06 85.58,85.6 85.37,85.6 85.15,85.38 85.15,85.16 85.69,84.63 85.69,84.42 85.47,84.2 85.25,84.2 84.72,84.73 84.5,84.73 84.29,84.52 84.29,84.3 84.82,83.77 84.82,83.55 84.61,83.34 84.39,83.34 83.86,83.87 83.64,83.87 83.43,83.65 83.43,83.44 83.96,82.91 83.96,82.69 83.74,82.47 83.53,82.47 83,83.01 82.78,83.01 82.56,82.79 82.56,82.58 83.1,82.04 83.1,81.83 82.88,81.61 82.67,81.61 82.13,82.15 81.92,82.15 81.7,81.93 81.7,81.71 82.24,81.18 82.24,80.97 82.02,80.75 81.8,80.75 81.27,81.28 81.05,81.28 80.84,81.07 80.84,80.85 81.37,80.32 81.37,80.1 81.16,79.89 80.94,79.89 80.41,80.42 80.19,80.42 79.98,80.2 79.98,79.99 80.51,79.46 80.51,79.24 80.29,79.02 80.08,79.02 79.54,79.56 79.33,79.56 79.11,79.34 79.11,79.13 79.65,78.59 79.65,78.38 79.43,78.16 79.22,78.16 78.68,78.7 78.47,78.7 78.25,78.48 78.25,78.26 78.78,77.73 78.78,77.51 78.51,77.24 77.22,77.24 77.06,77.39 77.06,77.57 76.91,77.72 76.61,77.72 76.45,77.57 76.45,77.39 76.3,77.24 75.72,77.24 74.42,75.95 61.98,75.95 59.39,73.36 58.62,73.36 58.09,72.82 57.87,72.82 57.33,73.37 57.11,73.37 56.89,73.15 56.89,72.94 57.44,72.39 57.44,72.17 56.77,71.5 56.77,70.23 56.21,69.68 55.47,69.68 55.27,69.47 55.27,68.97 55.27,68.97 55.27,68.05 v2(55.67,67.65)
